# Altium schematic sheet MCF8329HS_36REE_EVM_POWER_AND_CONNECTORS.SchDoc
size 431 x 279 mm; Date: Not shown in title block; ApprovedBy: Not shown in title block; CheckedBy: Not shown in title block; Author: Not shown in title block; CompanyName: Not shown in title block; Engineer: Not shown in title block; Organization: Not shown in title block; Address1: Not shown in title block; Address2: Not shown in title block; Address3: Not shown in title block; Address4: Not shown in title block; DocumentNumber: 4; Revision: Use project parameter SCH_Rev; SheetNumber: 4; SheetTotal: 5; PageSetup: Record=PageOptions¦CenterHorizontal=True¦CenterVertical=True¦PrintScale=1.00¦XCorrection=1.00¦YCorrection=1.00¦PrintKind=0¦BorderSize=5000000¦LeftOffset=0¦BottomOffset=0¦Orientation=2¦PaperLength=1000¦PaperWidth=1000¦Scale=100¦PaperSource=15¦PrintQuality=600¦MediaType=1¦DitherType=10¦PaperKind=Letter¦PrintScaleMode=1
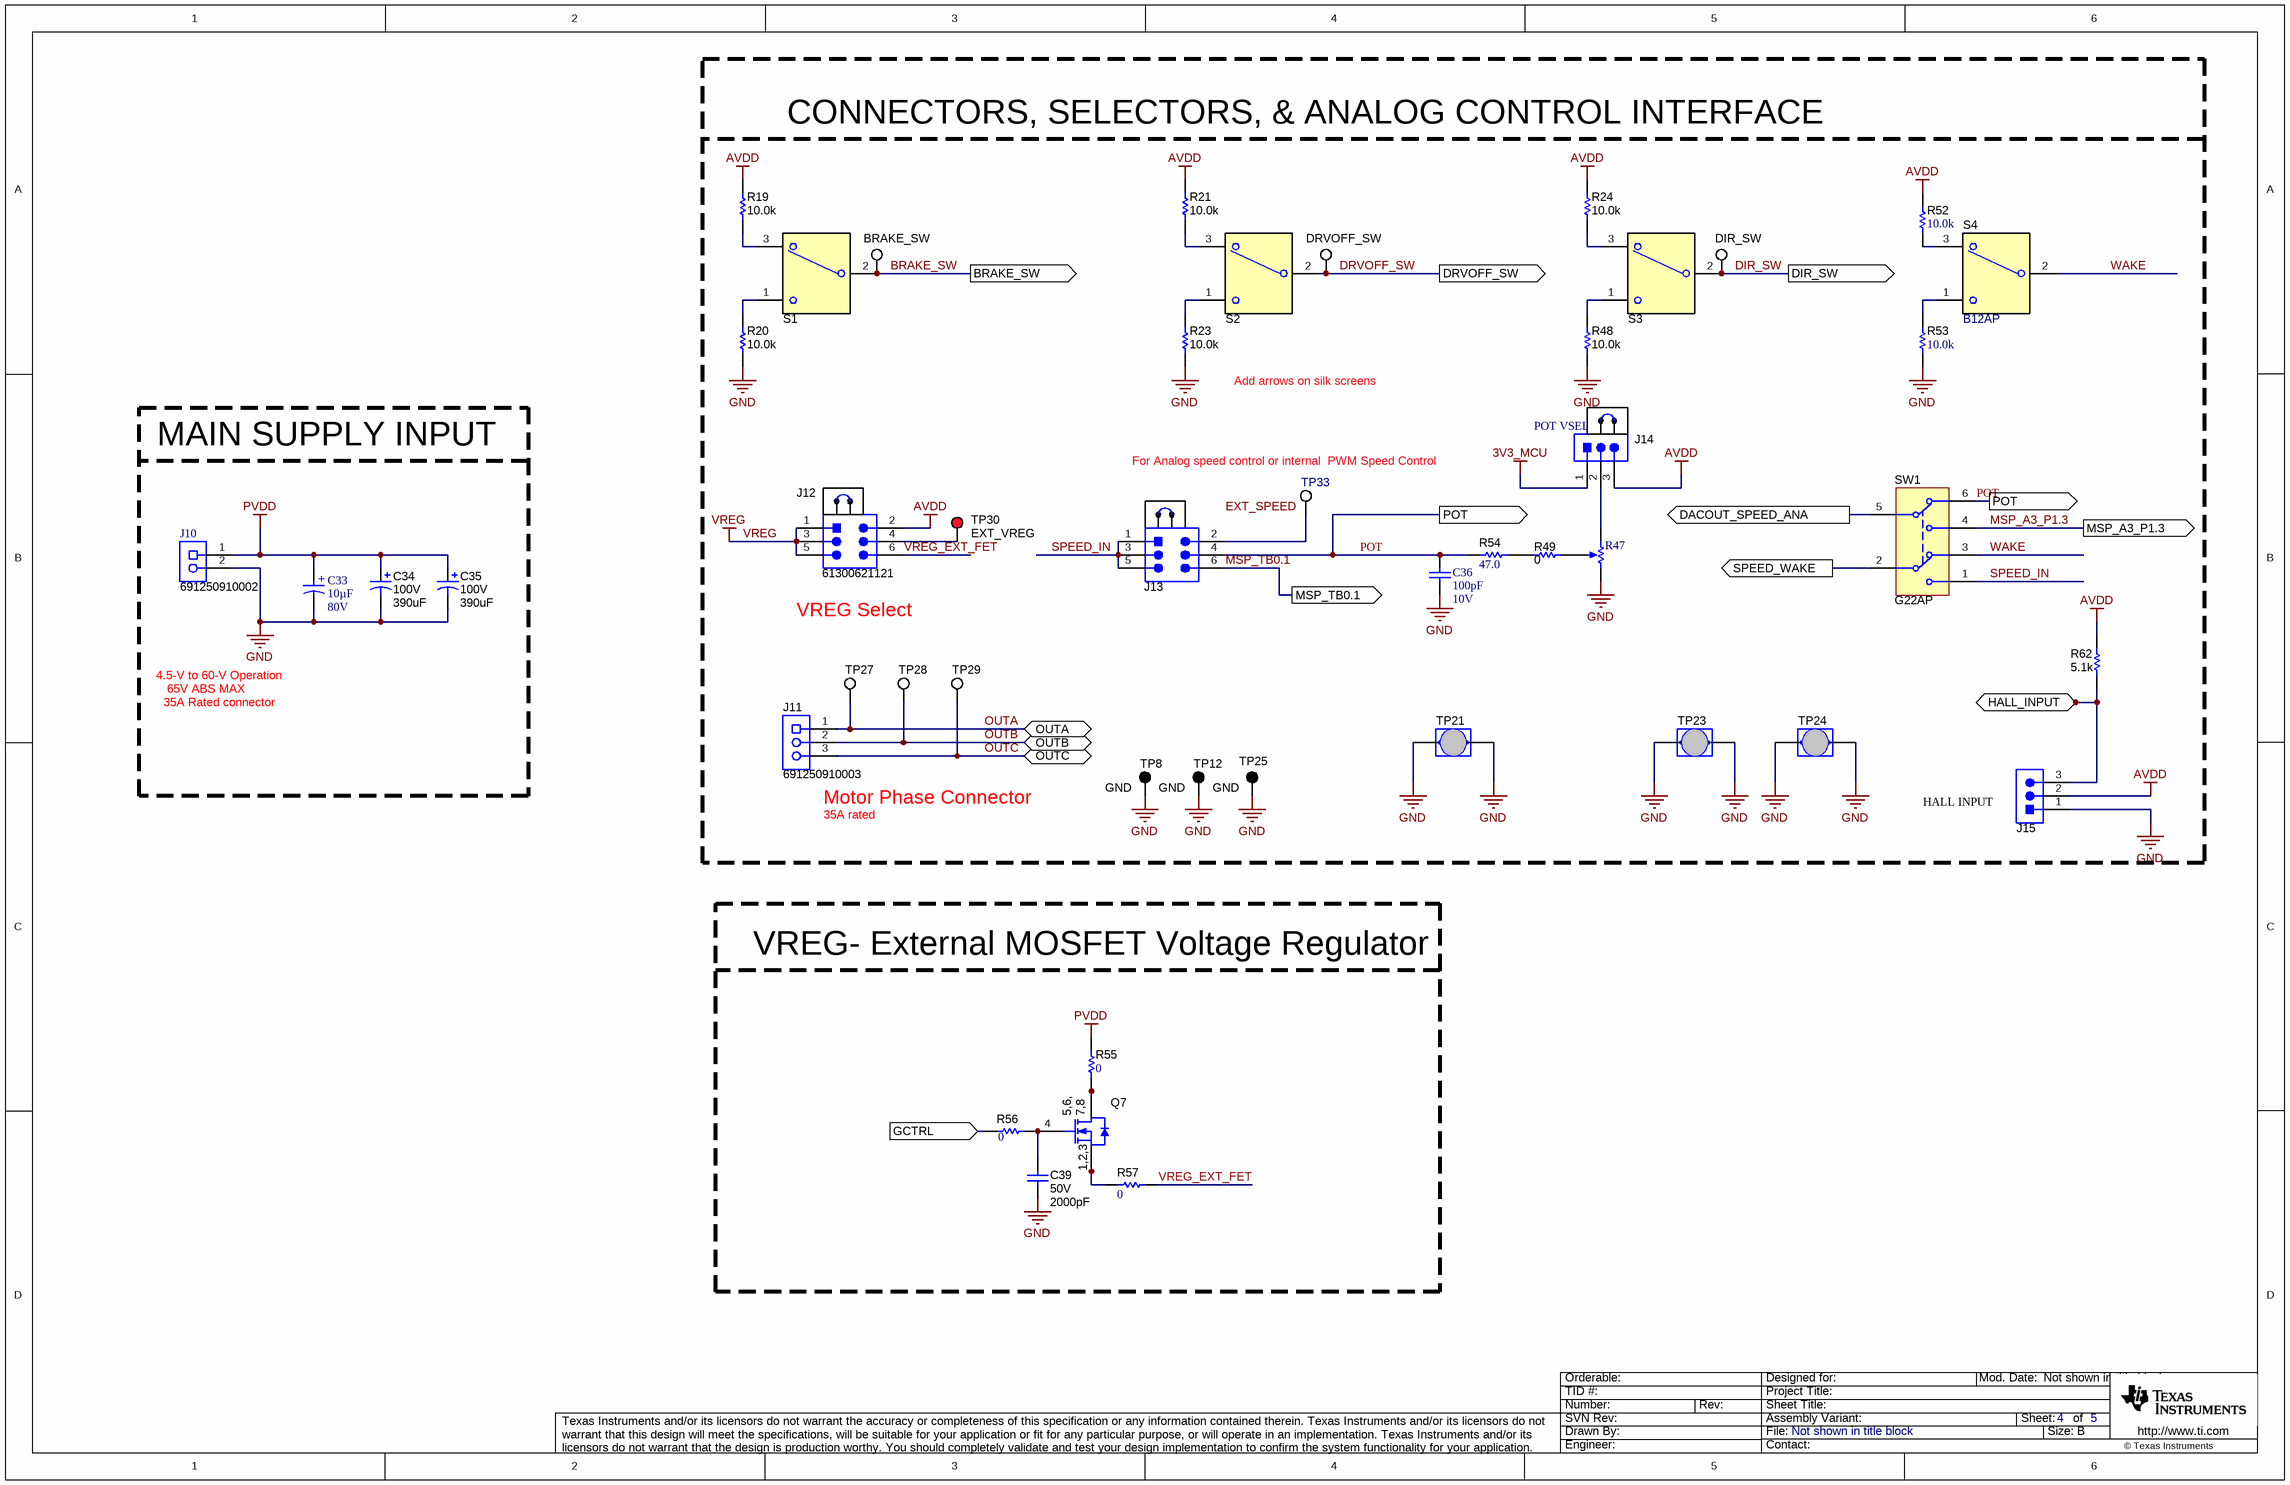
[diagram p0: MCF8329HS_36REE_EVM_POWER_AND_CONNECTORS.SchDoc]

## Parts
C33  Cap_F: 10µF  Rated Voltage (DC): 80V  [WCAP-ASLI_D6.3H7.7]  (hidden comment: 865081745005)
C34  VDC_V: 100V  ValueDisplayed: 390uF  [KYB_1250x3500]  (hidden comment: EKYB101ELL391MK35S)
C35  VDC_V: 100V  ValueDisplayed: 390uF  [KYB_1250x3500]  (hidden comment: EKYB101ELL391MK35S)
C36  Cap_F: 100pF  Rated Voltage (DC): 10V  [WCAP-CSGP_0603_L1.6W0.8H0.8_Reflow]  (hidden comment: 885012206003)
C39  VDC_V: 50V  ValueDisplayed: 2000pF  [1206]  (hidden comment: 12065A202JAT2A)
J10  691250910002  [FP-691250910002_CONN_TERM_BLK2-MFG]
J11  691250910003  [FP-691250910003_CONN_TERM_BLK3-MFG]
J12  61300621121  [Wurth_61300621121]
J13  Header_3x2  [Wurth_61300621121]  (value not drawn)
J14  61300311121  [WURTH_61300311121]  (value not drawn)
J15  61300311121  [WURTH_61300311121]  (value not drawn)
Q7  CSD18534Q5A  [DQJ0008A]  (value not drawn)
R19  ValueDisplayed: 10.0k  [0603L]  (hidden comment: ERA-3ARW103V)
R20  ValueDisplayed: 10.0k  [0603L]  (hidden comment: ERA-3ARW103V)
R21  ValueDisplayed: 10.0k  [0603L]  (hidden comment: ERA-3ARW103V)
R23  ValueDisplayed: 10.0k  [0603L]  (hidden comment: ERA-3ARW103V)
R24  ValueDisplayed: 10.0k  [0603L]  (hidden comment: ERA-3ARW103V)
R47  3352T-1-253LF  [Bourns_3352T]  (value not drawn)
R48  ValueDisplayed: 10.0k  [0603L]  (hidden comment: ERA-3ARW103V)
R49  ValueDisplayed: 0  [0603L]  (hidden comment: ERJ-3GEY0R00V)
R52  ValueDisplayed: 10.0k  [0603]  (hidden comment: ERA-3ARW103V)
R53  ValueDisplayed: 10.0k  [0603]  (hidden comment: ERA-3ARW103V)
R54  ValueDisplayed: 47.0  [0603]  (hidden comment: RT0603BRD0747RL)
R55  ValueDisplayed: 0  [0603]  (hidden comment: ERJ-3GEY0R00V)
R56  ValueDisplayed: 0  [0603]  (hidden comment: ERJ-3GEY0R00V)
R57  ValueDisplayed: 0  [0603]  (hidden comment: ERJ-3GEY0R00V)
R62  ValueDisplayed: 5.1k  [0603L]  (hidden comment: CRCW06035K10JNEA)
S1  SW_SPDT_COM2_1_3  [SW_B12AP]  (value not drawn)
S2  SW_SPDT_COM2_1_3  [SW_B12AP]  (value not drawn)
S3  SW_SPDT_COM2_1_3  [SW_B12AP]  (value not drawn)
S4  B12AP  [SW_B12AP]
SH-J7  60900213421  [Wurth_60900213421]  (value not drawn)
SH-J8  60900213421  [Wurth_60900213421]  (value not drawn)
SH-J25  60900213421  [Wurth_60900213421]  (value not drawn)
SW1  G22AP  [SW_G2xAP]
TP8  GND  [Keystone5001]
TP12  GND  [Keystone5001]
TP21  GND  [Harwin_D3082-05]  (value not drawn)
TP23  GND  [Harwin_D3082-05]  (value not drawn)
TP24  GND  [Harwin_D3082-05]  (value not drawn)
TP25  GND  [Keystone5001]
TP26  BRAKE_SW  [Keystone5002]
TP27  OUTA  [Testpoint_Keystone_Compact]  (value not drawn)
TP28  OUTB  [Testpoint_Keystone_Compact]  (value not drawn)
TP29  OUTC  [Testpoint_Keystone_Compact]  (value not drawn)
TP30  EXT_VREG  [Keystone5000]
TP31  DRVOFF_SW  [Keystone5002]
TP32  DIR_SW  [Keystone5002]
TP33  EXT_SPEED  [Keystone5002]  (value not drawn)

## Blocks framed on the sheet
CONNECTORS, SELECTORS, & ANALOG CONTROL INTERFACE: C36 J11-J15 R19-R21 R23 R24 R47-R49 R52-R54 R62 S1-S4 SH-J7 SH-J8 SH-J25 SW1 TP8 TP12 TP21 TP23-TP33
MAIN SUPPLY INPUT: C33-C35 J10
VREG- External MOSFET Voltage Regulator: C39 Q7 R55-R57

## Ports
BRAKE_SW (out), DACOUT_SPEED_ANA (out), DIR_SW (out), DRVOFF_SW (out), GCTRL (in), HALL_INPUT (bidir), MSP_A3_P1.3 (out), MSP_TB0.1 (out), OUTA (bidir), OUTB (bidir), OUTC (bidir), POT (out), SPEED_WAKE (out)

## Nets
3V3_MCU: J14.1
AVDD: J12.2 J14.3 J15.2 R19.2 R21.2 R24.2 R52.2 R62.1
GND: C33.2(N) C34.2(-) C35.2(-) C36.2 C39.2 J10.2 J15.1 R20.1 R23.1 R47.3(CW) R48.1 R53.1 TP8.1 TP12.1 TP21.1 TP21.2 TP23.1 TP23.2 TP24.1 TP24.2 TP25.1
PVDD: C33.1(P) C34.1(+) C35.1(+) J10.1 R55.2
VREG: J12.1 J12.3 J12.5
BRAKE_SW: S1.2(COM) TP26.1 ; port BRAKE_SW
DACOUT_SPEED_ANA: SW1.5 ; port DACOUT_SPEED_ANA
DIR_SW: S3.2(COM) TP32.1 ; port DIR_SW
DRVOFF_SW: S2.2(COM) TP31.1 ; port DRVOFF_SW
GCTRL: R56.1 ; port GCTRL
HALL_INPUT: J15.3 R62.2 ; port HALL_INPUT
MSP_A3_P1.3: SW1.4 ; port MSP_A3_P1.3
MSP_TB0.1: J13.6 ; port MSP_TB0.1
OUTA: J11.1 TP27.1 ; port OUTA
OUTB: J11.2 TP28.1 ; port OUTB
OUTC: J11.3 TP29.1 ; port OUTC
POT: C36.1 J13.4 R54.1 SW1.6 ; port POT
SPEED_IN: J13.1 J13.3 J13.5 SW1.1
SPEED_WAKE: SW1.2 ; port SPEED_WAKE
VREG_EXT_FET: J12.6 R57.2
WAKE: S4.2(COM) SW1.3
NetC39_1: C39.1 Q7.4(G) R56.2
NetJ12_4: J12.4 TP30.1
NetJ13_2: J13.2 TP33.1
NetJ14_2: J14.2 R47.1(CCW)
NetQ7_1: Q7.1(S) Q7.2(S) Q7.3(S) R57.1
NetQ7_5: Q7.5(D) Q7.6(D) Q7.7(D) Q7.8(D) Q7.9(D) R55.1
NetR19_1: R19.1 S1.3
NetR20_2: R20.2 S1.1
NetR21_1: R21.1 S2.3
NetR23_2: R23.2 S2.1
NetR24_1: R24.1 S3.3
NetR47_2: R47.2(WIPER) R49.2
NetR48_2: R48.2 S3.1
NetR49_1: R49.1 R54.2
NetR52_1: R52.1 S4.3
NetR53_2: R53.2 S4.1

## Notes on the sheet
- Add arrows on silk screens
- POT VSEL
- For Analog speed control or internal  PWM Speed Control
- VREG Select
- 65V ABS MAX
- 4.5-V to 60-V Operation
- 35A Rated connector
- (near J11) Motor Phase Connector
- 35A rated
- (near J15) HALL INPUT
- Labels drawn without touching a wire or pin: EXT_SPEED

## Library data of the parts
C33 = CMP-0110675-1: WCAP-ASLI Aluminum Electrolytic Capacitor, V-Chip, D6.3 x H7.7mm, 10uF, 80V; Manufacturer: Wurth Elektronik; Capacitance Tolerance: +/-20%; Dissipation Factor: 10%; Endurance: 2000h; Leakage Current: 8uA; Ripple Current: 35mA; Technical Reference: ASED077100M080DVCTCB000
C34 C35 = CMP-0009875-2: CAP, AL, 390 uF, 100 V, +/- 20%, 0.026 ohm, TH; Manufacturer: Chemi-Con; TaMin_C: -40°C; ESR_ohm: 0.026; Polarized: Y; SizeAreaWB_mm2: 210.25; U/M: EA; Value: 390uF; TaMax_C: 105°C; SizeZ_mm: 36.5; SizeX_mm: 12.5; Cap_Case: 12.5x35mm; SizeArea_mm2: 156.25; CompType: Capacitor; AEC Qualified: N; Cap_F: 390µF; IRMS_A: 2.25A; AEC Category: Q200
C36 = CMP-0119306-1: WCAP-CSGP Multilayer Ceramic Chip Capacitor, General Purpose, size 0603, X7R, 100pF, 10VDC; Manufacturer: Wurth Elektronik; Capacitance Tolerance: +/-10%; Case/Size Code: 0603; Dissipation Factor: 5%; Insulation Resistance: 10GOhm; Technical Reference: X7R0603101K010DFCT10000
C39 = CMP-0082630-1: CAP, CERM, 2000 pF, 50 V,+/- 5%, C0G/NP0, 1206; Manufacturer: AVX; Cap_F: 2nF; SizeAreaWB_mm2: 10.92; SizeArea_mm2: 5.12; AEC Qualified: N; AEC Category: Q200; Value: 2000pF; TaMax_C: 125°C; SizeZ_mm: 1.35; Green_REACh: Incomplete; TaMin_C: -55°C; SizeY_mm: 1.6; Green_Lifecycle: Active; U/M: EA; SizeX_mm: 3.2
J10 = CMP-0121275-2: 2 Position Wire to Board Terminal Block Horizontal with Board 0.375" (9.53mm) Through Hole; Manufacturer: Wurth Electronics; Current_A: 24A; Voltage_V: 300V; Row_Count: 1; AEC Qualified: No; Conn Gender: Female; DUT-Pitch_mm: 9.52mm; Is Female: yes; Max Wire Gauge: 10; Min Wire Gauge: 30; SizeZ_mm: 21.6mm
J11 = CMP-0121276-2: 3 Position Wire to Board Terminal Block Horizontal with Board 0.375" (9.53mm) Through Hole; Manufacturer: Wurth Electronics; Current_A: 24A; Voltage_V: 300V; Row_Count: 1; AEC Qualified: No; Conn Gender: Female; DUT-Pitch_mm: 9.52mm; Is Female: yes; Max Wire Gauge: 10; Min Wire Gauge: 30; SizeZ_mm: 21.6mm
J12 = CMP-0054802-2: Header, 2.54mm, 3x2, Gold, TH; Manufacturer: Wurth Elektronik; Pitch_mm: 2.54; Gender: Male; Green_REACh: Passed; Shrouded: N; Green_Lifecycle: Active; Row_Count: 2
J13 = CMP-0054802-2: Header, 2.54mm, 3x2, Gold, TH; PartNumber: 61300621121; Manufacturer: Wurth Elektronik; Pitch_mm: 2.54; Gender: Male; Shrouded: N; Row_Count: 2; Green_Lifecycle: Active; Green_REACh: Passed
J14 J15 = CMP-0054796-4: Header, 2.54 mm, 3x1, Gold, TH; Manufacturer: Wurth Elektronik; CNHeader: TRUE; CT: FALSE; Green_Lifecycle: Active; Green_REACh: Passed
Q7 = CMP-0000817-1: MOSFET, N-CH, 60 V, 50 A, DQJ0008A (VSONP-8); Alternate Manufacturer: None; Manufacturer: Texas Instruments; SizeZ_mm: 1.1; ChType: N; Value2: 22 nC; Value1: 0.009; VdsMax_V: 60V; SizeX_mm: 6; SizeY_mm: 4.9; Vgs_V: 2.3V; Value: 60V; Rdson45_ohm: 9.8m; SizeArea_mm2: 29.4; AEC Category: Q101; IdsMax_A: 50A; SizeAreaWB_mm2: 55.2; U/M: EA; QgTyp_nC: 22
R19-R21 R23 R24 R48 R52 R53 = CMP-0086251-1: RES, 10.0 k, 0.05%, 0.1 W, AEC-Q200 Grade 0, 0603; Manufacturer: Panasonic; Res_ohm: 10k; Value: 10.0k; SizeY_mm: 0.8; SizeArea_mm2: 1.28; SizeAreaWB_mm2: 4.68; AEC Grade: 0; Power_W: 100mW; SizeX_mm: 1.6; Value2: 0.1W; Value_Code: 10k0; SizeZ_mm: 1; AEC Qualified: Y; AEC Category: Q200; TempCo: 10 ppm/C
R47 = CMP-0001776-2: Trimmer Potentiometer, 25kohm, 0.5W, TH; Manufacturer: Bourns
R49 R55-R57 = CMP-0025874-4: RES, 0, 5%, 0.1 W, AEC-Q200 Grade 0, 0603; Manufacturer: Panasonic; Power_W: 100mW; TempCo: 600 ppm/C; Value_Code: 0000; Value: 0; EIA_Code: E24; SizeX_mm: 1.6; SizeY_mm: 0.8; SizeZ_mm: 1; Value2: 0.1W; SizeArea_mm2: 1.28; AEC Qualified: Y; VDC_V: 50V; AEC Category: Q200; SizeAreaWB_mm2: 4.68
R54 = CMP-0024269-3: RES, 47.0, 0.1%, 0.1 W, 0603; Manufacturer: Yageo America; Power_W: 100mW; TempCo: 25 ppm/C; Value_Code: 47R0; U/M: EA; Value: 47.0; EIA_Code: E192; Res_ohm: 47; SizeX_mm: 1.6; SizeY_mm: 0.8; SizeZ_mm: 1; Value2: 0.1W; SizeArea_mm2: 1.28; VDC_V: 75V; AEC Category: Q200
R62 = CMP-0025830-4: RES, 5.1 k, 5%, 0.1 W, AEC-Q200 Grade 0, 0603; Manufacturer: Vishay-Dale; Power_W: 100mW; TempCo: 200 ppm/C; Value_Code: 5k10; Value: 5.1k; EIA_Code: E24; SizeX_mm: 1.6; SizeY_mm: 0.8; SizeZ_mm: 1; Value2: 0.1W; SizeArea_mm2: 1.28; AEC Qualified: Y; VDC_V: 75V; AEC Category: Q200; AEC Grade: 0
S1-S3 = CMP-0002155-2: SWITCH TOGGLE SPDT 0.4VA 28V; PartNumber: B12AP; Manufacturer: NKK Switches; SwitchFunction: On-On; PositionCount: 2; CurrentRating_mA: 100A
S4 = CMP-0002155-2: SWITCH TOGGLE SPDT 0.4VA 28V; Manufacturer: NKK Switches; CurrentRating_mA: 100A; PositionCount: 2; SwitchFunction: On-On
SH-J7 SH-J8 SH-J25 = CMP-0003761-2: Shunt, 2.54mm, Gold, Black; Manufacturer: Wurth Elektronik; Value: 1x2
SW1 = CMP-0002204-2: Switch, DPDT, On-On, 0.4 VA, 28 V, TH; Manufacturer: NKK Switches; CurrentRating_mA: 400A; PositionCount: 2; VDC_V: 28V
TP8 TP12 TP25 = CMP-0055138-1: Test Point, Miniature, Black, TH; Manufacturer: Keystone; CNHeader: FALSE; Green_Lifecycle: Active; Green_REACh: Passed; ContactFinish: Silver; CT: TRUE
TP21 TP23 TP24 = CMP-0075110-1: 1mm Uninsulated Shorting Plug, 10.16mm spacing, TH; Manufacturer: Harwin; PartNumber: D3082-05; CNHeader: False; Green_Lifecycle: Active; Green_REACh: Passed; CompType: Jumper Wire
TP26 TP31-TP33 = CMP-0055139-1: Test Point, Miniature, White, TH; Manufacturer: Keystone; CNHeader: FALSE; Green_Lifecycle: Active; Green_REACh: Passed; ContactFinish: Silver; CT: TRUE
TP27-TP29 = CMP-0055153-1: Test Point, Compact, SMT; Manufacturer: Keystone; CNHeader: FALSE; Green_Lifecycle: Active; Green_REACh: Passed; CT: TRUE
TP30 = CMP-0055137-1: Test Point, Miniature, Red, TH; PartNumber: 5000; Manufacturer: Keystone; ContactFinish: Silver; CNHeader: FALSE; CT: TRUE; Green_Lifecycle: Active; Green_REACh: Passed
